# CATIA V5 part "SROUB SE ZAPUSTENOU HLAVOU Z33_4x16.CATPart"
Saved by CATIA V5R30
Part number: SROUB SE ZAPUSTENOU HLAVOU Z33/4x16
Bounding box of the stored display mesh (mm): x 0 to 16, y -3.991 to 3.991, z -4 to 4
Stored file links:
  C:\Users\ondra\Desktop\PŘÍLOHA P III\CATIA\SROUB SE ZAPUSTENOU HLAVOU Z33_4x16.CATPart
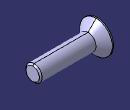
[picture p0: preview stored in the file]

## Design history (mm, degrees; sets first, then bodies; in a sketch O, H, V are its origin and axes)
Set1
  DatumSurface1 to DatumSurface24 "Z33/4x16"
  Join1: Elements (DatumSurface1; DatumSurface2; DatumSurface3; DatumSurface4; DatumSurface5; DatumSurface6; DatumSurface7; DatumSurface8; DatumSurface9; DatumSurface10; DatumSurface11; DatumSurface12; DatumSurface13; DatumSurface14; DatumSurface15; DatumSurface16; DatumSurface17; DatumSurface18; DatumSurface19; DatumSurface20; DatumSurface21; DatumSurface22; DatumSurface23; DatumSurface24)
Body1 (main body)
  CloseSurface1: CloseElement Join1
